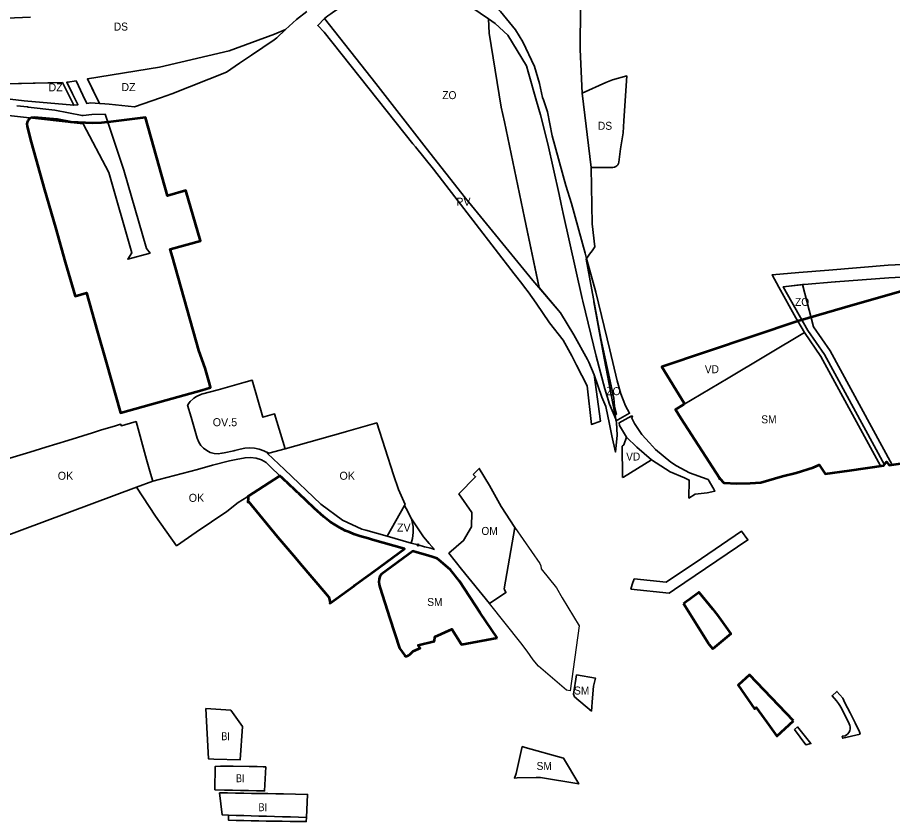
# Model space of a CAD drawing. Extents: x -650276 to -642489, y -1074311 to -1066658.
# Drawn here: x -648741 to -647428, y -1070372 to -1069166 of the extents above; entities that cross this region are included whole.
import ezdxf

# ---------------------------------------------------------------- set-up
doc = ezdxf.new("R2010")
doc.units = 0
doc.header["$LTSCALE"] = 4.8
doc.header["$PDMODE"] = 32
doc.header["$PDSIZE"] = 2.4
for name, color, linetype, lineweight in [('11', 7, 'Continuous', 35), ('12', 7, 'Continuous', 35), ('13', 7, 'Continuous', 35), ('15', 7, 'Continuous', 35), ('18', 7, 'Continuous', 35), ('2', 7, 'Continuous', 35), ('24', 7, 'Continuous', 35), ('25', 7, 'Continuous', 35), ('35', 7, 'Continuous', 35), ('40', 7, 'Continuous', 35), ('42', 7, 'Continuous', 35), ('60', 7, 'Continuous', 53), ('61', 7, 'Continuous', 25)]:
    doc.layers.add(name, color=color, linetype=linetype, lineweight=lineweight)
doc.layers.add('62', color=7, linetype='Continuous')

msp = doc.modelspace()

# ---------------------------------------------------------------- linework, layer by layer
at = {"layer": '11'}
msp.add_lwpolyline([(-648339.05, -1069812.45), (-648363.68, -1069819.31), (-648371.21, -1069815.56), (-648378.1, -1069813.29), (-648385.21, -1069811.91), (-648392.45, -1069811.44), (-648399.68, -1069811.88), (-648406.84, -1069813.23), (-648414.657, -1069815.246), (-648415.99, -1069815.59), (-648430.881, -1069818.663), (-648433.97, -1069819.3), (-648439.89, -1069819.97), (-648445.8, -1069819.51), (-648451.53, -1069817.98), (-648456.88, -1069815.39), (-648461.64, -1069811.86), (-648465.67, -1069807.49), (-648468.82, -1069802.44), (-648470.97, -1069796.9), (-648480.267, -1069765.316), (-648485.44, -1069747.39), (-648485.14, -1069746.55), (-648483.274, -1069743.777), (-648481.79, -1069741.57), (-648477.39, -1069737.44), (-648476.022, -1069736.525), (-648472.4, -1069734.1), (-648464.45, -1069730.89), (-648439.8, -1069724.19), (-648401.288, -1069713.154), (-648388.631, -1069709.738), (-648372.639, -1069765.241), (-648355.015, -1069760.287)], close=True, dxfattribs=at)
at = {"layer": '12'}
msp.add_lwpolyline([(-648057.11, -1069851.12), (-648053.61, -1069854.64), (-648078.54, -1069880.01), (-648059.32, -1069908.27), (-648059.5, -1069929.52), (-648071.58, -1069950.39), (-648093.67, -1069969.42), (-648074.96, -1069993.46), (-648032.85, -1070044.73), (-648008.18, -1070028.25), (-648010.44, -1070023.66), (-648010.94, -1070022.65), (-647994.71, -1069930.53), (-648015.11, -1069898.98), (-648032.94, -1069867.46), (-648048.08, -1069841.95)], close=True, dxfattribs=at)
at = {"layer": '13'}
msp.add_lwpolyline([(-648767.83, -1069946.87), (-648562.242, -1069870.301), (-648537.86, -1069861.22), (-648541.06, -1069849.78), (-648546.97, -1069828.68), (-648562.87, -1069771.85), (-648579.63, -1069776.66), (-648584.65, -1069778.1), (-648586.09, -1069775.75), (-648593.59, -1069778.06), (-648615.88, -1069784.93), (-648627.99, -1069788.67), (-648665.05, -1069799.99), (-648698.31, -1069810.16), (-648722.24, -1069817.54), (-648772.48, -1069832.83)], dxfattribs=at)
for points in [[(-648159.1, -1069896.39), (-648169.15, -1069873.81), (-648176.78, -1069851.74), (-648201.83, -1069773.86), (-648247.27, -1069786.64), (-648251.94, -1069787.95), (-648339.05, -1069812.45), (-648363.68, -1069819.31), (-648365.81, -1069819.9), (-648340.38, -1069843.78), (-648285.62, -1069895.71), (-648253.13, -1069919.7), (-648223.99, -1069932.96), (-648218.245, -1069934.595), (-648186.268, -1069943.697), (-648160.04, -1069897.73)], [(-648470.79, -1069843.51), (-648528.11, -1069858.73), (-648537.86, -1069861.22), (-648562.242, -1069870.301), (-648533.79, -1069913.49), (-648502.048, -1069957.969), (-648472.6, -1069937.81), (-648426.82, -1069906.88), (-648409.44, -1069893.25), (-648396.87, -1069885.43), (-648395.03, -1069884.22), (-648347.06, -1069853), (-648361.3, -1069839.7), (-648367.64, -1069833.35), (-648374.89, -1069829.22), (-648382.8, -1069826.55), (-648391.08, -1069825.45), (-648399.4, -1069825.97), (-648412.74, -1069828.72), (-648422.75, -1069830.78), (-648422.75, -1069830.78), (-648447.98, -1069837.44)]]:
    msp.add_lwpolyline(points, close=True, dxfattribs=at)
at = {"layer": '15'}
for points in [[(-648147.81, -1069355.26), (-648143.81, -1069359.39), (-648116.93, -1069393.25), (-648052.62, -1069476.32), (-647995.61, -1069549.95), (-647984.36, -1069564.49), (-647980.21, -1069569.97), (-647974.74, -1069577.39), (-647962.93, -1069594.39), (-647942.48, -1069623.82), (-647922.32, -1069649.56), (-647909.25, -1069673.35), (-647902.18, -1069687.23), (-647886.43, -1069718.16), (-647879.96, -1069776.1), (-647866.4, -1069771.43), (-647866.4, -1069771.43), (-647875.82, -1069701.85), (-647883.51, -1069682.71), (-647885.665, -1069678.788), (-647906.16, -1069641.48), (-647925.99, -1069608.57), (-647967.53, -1069559.94), (-648068.71, -1069436.57), (-648127.77, -1069361.38), (-648203.01, -1069264.73), (-648280.1, -1069166.97), (-648290.39, -1069177.69), (-648280.46, -1069187.61), (-648147.81, -1069355.26)], [(-647815.788, -1070007.72), (-647767.622, -1070012.66), (-647714.989, -1069977.087), (-647654.577, -1069936.255), (-647645.274, -1069949.279), (-647755.356, -1070023.682), (-647763.476, -1070029.17), (-647820.515, -1070023.319), (-647818.81, -1070016.41)], [(-647493.13, -1070225.217), (-647492.138, -1070227.681), (-647491.692, -1070229.974), (-647491.767, -1070233.217), (-647492.286, -1070235.393), (-647493.254, -1070237.6), (-647495.889, -1070240.926), (-647499.448, -1070243.223), (-647503.6, -1070243.95), (-647502.82, -1070246.91), (-647476.94, -1070240.79), (-647477.78, -1070237.42), (-647484.35, -1070223.91), (-647491.97, -1070208.95), (-647499.68, -1070193.54), (-647502.99, -1070186.94), (-647511.73, -1070176.61), (-647518.813, -1070183.069), (-647512.222, -1070190.785), (-647509.223, -1070194.61), (-647507.054, -1070197.854), (-647505.688, -1070200.172), (-647504.419, -1070202.575)], [(-647575.15, -1070233.71), (-647570.887, -1070229.877), (-647550.603, -1070254.911), (-647558.19, -1070256.86)], [(-647575.15, -1070233.71), (-647558.19, -1070256.86), (-647550.603, -1070254.911), (-647570.887, -1070229.877)], [(-648307.13, -1070365.57), (-648319.33, -1070365.32), (-648331.32, -1070364.96), (-648343.31, -1070364.61), (-648355.27, -1070364.25), (-648367.26, -1070363.9), (-648378.49, -1070363.57), (-648389.95, -1070363.23), (-648401.36, -1070362.89), (-648412.88, -1070362.55), (-648424.31, -1070362.21), (-648424.05, -1070370), (-648412.75, -1070370.28), (-648401.35, -1070370.5), (-648390.06, -1070370.72), (-648378.73, -1070370.94), (-648367.67, -1070371.16), (-648355.67, -1070371.28), (-648343.67, -1070371.41), (-648331.67, -1070371.53), (-648319.67, -1070371.65), (-648307.67, -1070371.78)]]:
    msp.add_lwpolyline(points, close=True, dxfattribs=at)
for points in [[(-648929.112, -1069293.123), (-648642.241, -1069324.949), (-648603.386, -1069398.357), (-648569.22, -1069518.4), (-648575.15, -1069528.35), (-648541.88, -1069518.95), (-648547.3, -1069512.136), (-648581.051, -1069394.771), (-648609.304, -1069310.668), (-648629.16, -1069310.91), (-648641.98, -1069312.45), (-648643.83, -1069312.66), (-648684.39, -1069304.67), (-648724.82, -1069299.92), (-648725.82, -1069299.81), (-648741.58, -1069298.16)], [(-647341.697, -1069532.602), (-647434.969, -1069537.141), (-647523.931, -1069544.499), (-647568.792, -1069548.21), (-647608.81, -1069551.868), (-647598.735, -1069570.026), (-647573.15, -1069616.16), (-647570.37, -1069621.18), (-647560.36, -1069638.39), (-647535.588, -1069674.163), (-647446.322, -1069838.338), (-647441.19, -1069837.6), (-647440.46, -1069836.558), (-647530.471, -1069671.013), (-647555.266, -1069635.207), (-647592.199, -1069569.411), (-647560.836, -1069566.036), (-647514.067, -1069562.282), (-647513.66, -1069562.249), (-647433.779, -1069556.106), (-647433.779, -1069556.106), (-647356.899, -1069552.034)], [(-648149.67, -1069917.83), (-648147, -1069929), (-648147, -1069938), (-648148, -1069947), (-648150, -1069954), (-648139.78, -1069956.93)], [(-648115.23, -1069963.75), (-648123.45, -1069954.79), (-648131.5, -1069944.75), (-648149.67, -1069917.83)], [(-648139.78, -1069956.93), (-648130.36, -1069959.62), (-648120.68, -1069961.63), (-648115.23, -1069963.75)]]:
    msp.add_lwpolyline(points, dxfattribs=at)
msp.add_point((-648139.78, -1069956.93), dxfattribs=at)
at = {"layer": '18'}
for points in [[(-647560.36, -1069638.39), (-647674.901, -1069706.701), (-647742.36, -1069746.93)], [(-647446.322, -1069838.338), (-647535.588, -1069674.163), (-647560.36, -1069638.39)], [(-647742.36, -1069746.93), (-647752.32, -1069752.95), (-647753.7, -1069753.9)], [(-647753.7, -1069753.9), (-647751.66, -1069757.12), (-647745.84, -1069766.71), (-647737.17, -1069780.85), (-647700.58, -1069837.2), (-647687.45, -1069857.15), (-647681.51, -1069863.72)], [(-647641.78, -1069864.26), (-647625.83, -1069863.19), (-647593.07, -1069853.74), (-647583.62, -1069851.13), (-647572.63, -1069848.63), (-647559.47, -1069844.92), (-647547.12, -1069840.87), (-647538.34, -1069836.68), (-647536.82, -1069838.87), (-647531.33, -1069847.23), (-647529.5, -1069849.99), (-647500.03, -1069846.28), (-647492.76, -1069845.02), (-647446.322, -1069838.338)], [(-647681.51, -1069863.72), (-647661.79, -1069864.92), (-647641.78, -1069864.26)], [(-648182.01, -1070067.11), (-648197.23, -1070020.37), (-648198.22, -1070016.4), (-648198.48, -1070012.3), (-648198.17, -1070008.05), (-648197.19, -1070003.94), (-648194.84, -1070000.49), (-648147.46, -1069966.19)], [(-648147.46, -1069966.19), (-648140.96, -1069968.01), (-648128.48, -1069971.7)], [(-648128.48, -1069971.7), (-648118.75, -1069974.53), (-648111.44, -1069977.32)], [(-648111.44, -1069977.32), (-648105.79, -1069981.56), (-648091.06, -1069994.07), (-648077.68, -1070011.06), (-648046.83, -1070058.62), (-648021.35, -1070096.14), (-648074.76, -1070106.17)], [(-648152.35, -1070121.05), (-648153.85, -1070122.38), (-648156.07, -1070123.54), (-648159.02, -1070123.71), (-648159.89, -1070122.49), (-648167.48, -1070111.75), (-648182.01, -1070067.11)], [(-648074.76, -1070106.17), (-648089.22, -1070083.27), (-648114.7, -1070094.68), (-648115.11, -1070101.26), (-648139.91, -1070107.48), (-648136.61, -1070111.97)], [(-648136.61, -1070111.97), (-648139.45, -1070112.79), (-648147.02, -1070116.35), (-648152.35, -1070121.05)]]:
    msp.add_lwpolyline(points, dxfattribs=at)
for points in [[(-647902.17, -1070151.64), (-647906.6, -1070180.65), (-647905.17, -1070184.5), (-647879.81, -1070206.08), (-647878.18, -1070186.33), (-647876.74, -1070168.88), (-647873.97, -1070156.58)], [(-647962.82, -1070305.9), (-647956.36, -1070305.77), (-647898.82, -1070315.51), (-647921.51, -1070276.76), (-647979.24, -1070260.71), (-647983.6, -1070259.5), (-647992.71, -1070300.01), (-647995.46, -1070306.55), (-647991.12, -1070306.46)]]:
    msp.add_lwpolyline(points, close=True, dxfattribs=at)
msp.add_point((-647687.45, -1069857.15), dxfattribs=at)
at = {"layer": '2'}
msp.add_lwpolyline([(-648458.28, -1070202.26), (-648454.038, -1070277.767), (-648446.18, -1070278.15), (-648406.8, -1070279.32), (-648403.04, -1070229.15), (-648420.7, -1070204.96)], close=True, dxfattribs=at)
for points in [[(-648368.25, -1070289.71), (-648372.1, -1070289.59), (-648380.97, -1070289.44), (-648392.94, -1070289.25), (-648416.93, -1070288.85), (-648420.39, -1070288.79), (-648428.98, -1070288.92), (-648435.93, -1070288.95), (-648444.15, -1070289.16), (-648444.85, -1070324.47)], [(-648444.85, -1070324.47), (-648444.85, -1070324.47), (-648430.02, -1070324.76), (-648418.1, -1070325), (-648406.09, -1070325.23), (-648394.08, -1070325.47), (-648382.06, -1070325.7), (-648370.07, -1070325.94), (-648368.25, -1070289.71)], [(-648307.13, -1070365.57), (-648305.47, -1070331.23), (-648341.46, -1070330.48), (-648353.32, -1070330.23), (-648365.35, -1070329.98), (-648389.43, -1070329.58), (-648401.41, -1070329.39), (-648413.45, -1070329.19), (-648425.43, -1070329), (-648437.65, -1070328.8), (-648433.46, -1070361.94), (-648424.31, -1070362.21), (-648412.88, -1070362.55)], [(-648412.88, -1070362.55), (-648401.36, -1070362.89), (-648389.95, -1070363.23), (-648378.49, -1070363.57), (-648367.26, -1070363.9), (-648355.27, -1070364.25), (-648343.31, -1070364.61), (-648331.32, -1070364.96), (-648319.33, -1070365.32)]]:
    msp.add_lwpolyline(points, dxfattribs=at)
at = {"layer": '24'}
for points in [[(-648918.889, -1069268.875), (-648673.267, -1069262.895), (-648656.242, -1069297.116), (-648650.06, -1069296.39), (-648650.58, -1069295.34), (-648658.18, -1069280.27), (-648666.827, -1069262.738), (-648665.007, -1069262.694), (-648665.007, -1069262.694), (-648652.716, -1069260.657), (-648642.74, -1069281.93), (-648636.85, -1069294.49), (-648630.82, -1069293.63), (-648617.434, -1069294.508), (-648635.818, -1069257.857), (-648527.693, -1069239.938), (-648423.173, -1069215.44), (-648354.978, -1069190.492), (-648338.523, -1069183.389), (-648322.14, -1069168.56), (-648306.83, -1069156.57)], [(-648721.315, -1069164.952), (-648781.015, -1069167.44)]]:
    msp.add_lwpolyline(points, dxfattribs=at)
msp.add_lwpolyline([(-647860.52, -1069390.72), (-647848.24, -1069390.65), (-647845.25, -1069390.07), (-647843.41, -1069389.23), (-647841.81, -1069387.99), (-647840.42, -1069386.51), (-647839.4, -1069384.73), (-647838.79, -1069382.86), (-647836.2, -1069362.68), (-647832.29, -1069338.58), (-647832.29, -1069338.58), (-647831.19, -1069320.69), (-647830.23, -1069305.38), (-647826.928, -1069253.199), (-647848.17, -1069259.21), (-647858.37, -1069263.03), (-647893.553, -1069279.017), (-647880.326, -1069390.832)], close=True, dxfattribs=at)
at = {"layer": '25'}
msp.add_line((-647862.266, -1069668.613), (-647843.449, -1069768.252), dxfattribs=at)
for points in [[(-647893.553, -1069279.017), (-647896.67, -1069213.573), (-647896.362, -1069149.171), (-647886.615, -1069053.052)], [(-648036.291, -1069139.458), (-648031.92, -1069142.67), (-648016.36, -1069156.54), (-647993.8, -1069184.11)], [(-648005.47, -1069192.09), (-648024.02, -1069174.7), (-648034.421, -1069167.61)], [(-648034.421, -1069167.61), (-648034.421, -1069167.61), (-648033, -1069189), (-648015, -1069300), (-648010.092, -1069322.087), (-647980.331, -1069465.915), (-647958.34, -1069570.699), (-647925.99, -1069608.57), (-647906.16, -1069641.48), (-647885.665, -1069678.788), (-647885.663, -1069678.794), (-647883.51, -1069682.71), (-647875.82, -1069701.85), (-647875.82, -1069701.85), (-647864.19, -1069735.12), (-647858.44, -1069749.43), (-647852.63, -1069775.7), (-647850.66, -1069785.74), (-647849.165, -1069793.367)], [(-648526.15, -1069286.21), (-648508.95, -1069280.01), (-648427.08, -1069247.75), (-648407.73, -1069233.88), (-648389.91, -1069221.86), (-648355.81, -1069198.88), (-648351.77, -1069195.88), (-648338.523, -1069183.389), (-648354.978, -1069190.492)], [(-647993.8, -1069184.11), (-647982.58, -1069202.33), (-647965.06, -1069238.95), (-647957.56, -1069264.74), (-647953.01, -1069285.73), (-647951.841, -1069289.09)], [(-648354.978, -1069190.492), (-648423.173, -1069215.44), (-648527.693, -1069239.938), (-648635.818, -1069257.857)], [(-647962.2, -1069290.88), (-647974.81, -1069246.86), (-647977.29, -1069238.21), (-648005.47, -1069192.09)], [(-648635.818, -1069257.857), (-648622.995, -1069283.455), (-648617.434, -1069294.508)], [(-648617.434, -1069294.508), (-648609.425, -1069295.033), (-648603.228, -1069295.53), (-648565.18, -1069299.46), (-648526.15, -1069286.21)], [(-647852.78, -1069745.71), (-647859.722, -1069722.428), (-647872.87, -1069673.56), (-647892.79, -1069591.06), (-647892.789, -1069591.06), (-647893.75, -1069587.08), (-647922.04, -1069459.71), (-647925.16, -1069445.68), (-647928.41, -1069431.03), (-647945.28, -1069355.1), (-647956.27, -1069311.58), (-647962.2, -1069290.88)], [(-647951.841, -1069289.09), (-647945.63, -1069306.95), (-647938.77, -1069343.17), (-647918.08, -1069417.43), (-647909.67, -1069444.46), (-647889.22, -1069519.32), (-647887.087, -1069527.229), (-647885.782, -1069525.389), (-647882.551, -1069520.835), (-647878.73, -1069515.45)], [(-647880.326, -1069390.832), (-647880.326, -1069390.832), (-647893.553, -1069279.017)], [(-647878.73, -1069515.45), (-647874.75, -1069509.84), (-647878.93, -1069475.09), (-647880.318, -1069391.297), (-647880.326, -1069390.832)], [(-647843.449, -1069768.252), (-647844.371, -1069761.991), (-647842.438, -1069760.647), (-647845.086, -1069748.753), (-647846.484, -1069736.663), (-647855.158, -1069695.232), (-647865.69, -1069647.32), (-647876.061, -1069592.206), (-647862.266, -1069668.613)], [(-647841.402, -1069792.351), (-647842.489, -1069773.282), (-647842.622, -1069770.956), (-647843.337, -1069769.013), (-647843.443, -1069768.293), (-647852.78, -1069745.71)], [(-647849.165, -1069793.367), (-647843.74, -1069817.63), (-647841.402, -1069792.351)]]:
    msp.add_lwpolyline(points, dxfattribs=at)
msp.add_lwpolyline([(-648730.66, -1069290.43), (-648656.242, -1069297.116), (-648673.267, -1069262.895), (-648761.189, -1069265.035), (-648918.889, -1069268.875), (-648909.86, -1069270.02), (-648861.49, -1069275.34), (-648785.92, -1069284.2), (-648730.66, -1069290.43)], close=True, dxfattribs=at)
msp.add_arc((-648354.978, -1069190.492), 0.000000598, 264.13978, 298.69712, dxfattribs=at)
at = {"layer": '35'}
for points in [[(-647356.899, -1069552.034), (-647433.779, -1069556.106), (-647433.779, -1069556.106), (-647513.66, -1069562.249), (-647514.067, -1069562.282), (-647560.836, -1069566.036), (-647563.104, -1069566.28)], [(-647563.104, -1069566.28), (-647546.777, -1069629.901), (-647521.943, -1069665.763)], [(-647521.943, -1069665.763), (-647428.993, -1069836.714), (-647369.3, -1069828.22)]]:
    msp.add_lwpolyline(points, dxfattribs=at)
for points in [[(-647740.74, -1069744.24), (-647742.36, -1069746.93), (-647674.901, -1069706.701), (-647560.36, -1069638.39), (-647570.37, -1069621.18), (-647701.61, -1069665.279), (-647774.11, -1069689.64)], [(-647833.172, -1069855.944), (-647833.172, -1069855.944), (-647831.62, -1069854.99), (-647789.55, -1069829.12), (-647811.83, -1069810.39), (-647827.16, -1069795.32), (-647831.32, -1069806.56), (-647833.91, -1069808.91), (-647833.2, -1069854.15)]]:
    msp.add_lwpolyline(points, close=True, dxfattribs=at)
at = {"layer": '40'}
msp.add_lwpolyline([(-648150, -1069954), (-648148, -1069947), (-648147, -1069938), (-648147, -1069929), (-648149.67, -1069917.83), (-648157.81, -1069902.06), (-648160.04, -1069897.73), (-648186.268, -1069943.697)], close=True, dxfattribs=at)
at = {"layer": '42'}
for points in [[(-648015, -1069300), (-648033, -1069189), (-648034.421, -1069167.61), (-648071.9, -1069142.06), (-648073.66, -1069140.86), (-648141.92, -1069121.66), (-648171.14, -1069122.83), (-648207.77, -1069129.95), (-648209.89, -1069130.36), (-648226.51, -1069136.57), (-648248.14, -1069144.65), (-648268.87, -1069158.61), (-648270.92, -1069159.99), (-648275.19, -1069162.87), (-648280.1, -1069166.97), (-648203.01, -1069264.73), (-648127.77, -1069361.38), (-648068.71, -1069436.57), (-647967.53, -1069559.94), (-647958.214, -1069571.3), (-647980.331, -1069465.915), (-648010.092, -1069322.087)], [(-647828.61, -1069748.41), (-647835.76, -1069730.01), (-647841.26, -1069710.69), (-647852.44, -1069664.03), (-647873.43, -1069577.87), (-647887.087, -1069527.229), (-647887.649, -1069528.021), (-647865.69, -1069647.32), (-647855.158, -1069695.232), (-647846.484, -1069736.663), (-647845.086, -1069748.753), (-647842.438, -1069760.647), (-647844.371, -1069761.991), (-647843.337, -1069769.013), (-647842.798, -1069770.477), (-647840.49, -1069769.3), (-647822.54, -1069759.29)], [(-647555.266, -1069635.207), (-647530.471, -1069671.013), (-647440.46, -1069836.558), (-647437.46, -1069832.27), (-647433.32, -1069837.33), (-647428.993, -1069836.714), (-647521.943, -1069665.763), (-647546.777, -1069629.901), (-647563.104, -1069566.28), (-647592.199, -1069569.411)], [(-647804.02, -1069791.01), (-647815.36, -1069774.66), (-647819.78, -1069765.84), (-647818.28, -1069764.99), (-647818.73, -1069763.53), (-647820.09, -1069763.65), (-647838, -1069773.63), (-647837.93, -1069777.45), (-647827.16, -1069795.32), (-647811.83, -1069810.39), (-647789.55, -1069829.12), (-647761.54, -1069847.24), (-647740.46, -1069856.29), (-647733.06, -1069859.46), (-647733.71, -1069886.65), (-647724.35, -1069880.48), (-647706.39, -1069878.81), (-647694.63, -1069876.07), (-647696.25, -1069873.35), (-647704.99, -1069858.7), (-647706.44, -1069857.98), (-647732.93, -1069848.5), (-647752.25, -1069837.95), (-647760.79, -1069832.61), (-647783.96, -1069813.49), (-647792.84, -1069803.65)]]:
    msp.add_lwpolyline(points, close=True, dxfattribs=at)
at = {"layer": '60'}
for points in [[(-648726.23, -1069329), (-648720.26, -1069352.66), (-648699.95, -1069424.34), (-648683.77, -1069480.8), (-648668.96, -1069532.87), (-648654.264, -1069583.761), (-648636.98, -1069578.86), (-648620.94, -1069635.45), (-648607.53, -1069682.78), (-648585.959, -1069758.915), (-648518.24, -1069739.91), (-648464.32, -1069724.64), (-648450.939, -1069720.921), (-648452.25, -1069716.34), (-648459.27, -1069691.81), (-648468.49, -1069665.23), (-648508.35, -1069524.48), (-648511.542, -1069513.207), (-648465.94, -1069500.68), (-648488.2, -1069425.34), (-648515.4, -1069433.05), (-648548.56, -1069315.61), (-648600.64, -1069321.87), (-648614.51, -1069323.62), (-648627.48, -1069324.05), (-648660.81, -1069322.69), (-648681.2, -1069318.86), (-648715.26, -1069315.58), (-648720.16, -1069316.01), (-648723.27, -1069318.05), (-648725.43, -1069321.26), (-648726.48, -1069324.93)], [(-648205.77, -1069996.14), (-648160.27, -1069962.63), (-648208.27, -1069949.26), (-648214.42, -1069947.46), (-648227.23, -1069943.8), (-648236.06, -1069940.52), (-648242.53, -1069937.92), (-648248.62, -1069935.54), (-648254.18, -1069932.68), (-648260.08, -1069929.44), (-648265.24, -1069926.2), (-648271.62, -1069922.1), (-648281.22, -1069914.79), (-648295.88, -1069901.64), (-648318.63, -1069879.94), (-648321, -1069877.7), (-648323.3, -1069875.52), (-648325.6, -1069873.34), (-648327.82, -1069871.23), (-648330.09, -1069869.08), (-648332.31, -1069866.98), (-648334.54, -1069864.87), (-648336.73, -1069862.79), (-648339.13, -1069860.51), (-648343.37, -1069856.49), (-648347.06, -1069853), (-648395.03, -1069884.22), (-648394.65, -1069886.59), (-648395.15, -1069892.61), (-648394.35, -1069891.95), (-648350.48, -1069944.78), (-648323.69, -1069976.45), (-648316.73, -1069984.68), (-648278.69, -1070029.47), (-648273.67, -1070035.38), (-648271.65, -1070043.3), (-648271.95, -1070044.31), (-648271.5, -1070043.98), (-648235.74, -1070018.05), (-648234.79, -1070017.36), (-648227.16, -1070011.83)], [(-647741.98, -1070044.74), (-647737.34, -1070041.32), (-647732.47, -1070037.73), (-647718.564, -1070027.479), (-647698.172, -1070052.962), (-647690.674, -1070062.331), (-647683.145, -1070072.735), (-647673.357, -1070086.635), (-647670.687, -1070090.426), (-647697.889, -1070112.941), (-647702.57, -1070106.56), (-647704.02, -1070104.5)], [(-647576.812, -1070220.636), (-647642.855, -1070151.617), (-647648.73, -1070157.05), (-647653.52, -1070161.48), (-647659.831, -1070167.317), (-647635.1, -1070202.5), (-647632.56, -1070200.72), (-647616.6, -1070223), (-647601.726, -1070243.764)]]:
    msp.add_lwpolyline(points, close=True, dxfattribs=at)
for points in [[(-647375.71, -1069564.91), (-647499.63, -1069600.73), (-647570.37, -1069621.18), (-647774.11, -1069689.64), (-647740.74, -1069744.24), (-647742.36, -1069746.93), (-647753.7, -1069753.9), (-647745.84, -1069766.71), (-647687.45, -1069857.15), (-647681.51, -1069863.72), (-647661.79, -1069864.92), (-647641.78, -1069864.26), (-647625.83, -1069863.19), (-647593.07, -1069853.74), (-647572.63, -1069848.63), (-647547.12, -1069840.87), (-647538.34, -1069836.68), (-647531.33, -1069847.23), (-647529.5, -1069849.99), (-647492.76, -1069845.02), (-647441.19, -1069837.6), (-647437.46, -1069832.27), (-647433.32, -1069837.33), (-647369.3, -1069828.22)], [(-648128.48, -1069971.7), (-648140.96, -1069968.01), (-648147.46, -1069966.19), (-648194.84, -1070000.49)], [(-648111.44, -1069977.32), (-648118.75, -1069974.53), (-648128.48, -1069971.7)], [(-648021.35, -1070096.14), (-648046.83, -1070058.62), (-648077.68, -1070011.06), (-648091.06, -1069994.07), (-648105.79, -1069981.56), (-648111.44, -1069977.32)], [(-648194.84, -1070000.49), (-648197.19, -1070003.94), (-648198.17, -1070008.05), (-648198.48, -1070012.3), (-648198.22, -1070016.4), (-648197.23, -1070020.37), (-648182.01, -1070067.11)], [(-648182.01, -1070067.11), (-648167.48, -1070111.75), (-648159.89, -1070122.49), (-648159.02, -1070123.71), (-648156.07, -1070123.54)], [(-648115.11, -1070101.26), (-648114.7, -1070094.68), (-648089.22, -1070083.27), (-648074.76, -1070106.17), (-648021.35, -1070096.14)], [(-648152.35, -1070121.05), (-648147.02, -1070116.35), (-648139.45, -1070112.79), (-648136.61, -1070111.97), (-648139.91, -1070107.48), (-648115.11, -1070101.26)], [(-648156.07, -1070123.54), (-648153.85, -1070122.38), (-648152.35, -1070121.05)]]:
    msp.add_lwpolyline(points, dxfattribs=at)
at = {"layer": '61'}
msp.add_lwpolyline([(-648008.18, -1070028.25), (-648010.94, -1070022.65), (-647994.71, -1069930.53), (-647957.24, -1069984.73), (-647955.65, -1069988.28), (-647955.08, -1069992.58), (-647932.43, -1070021.22), (-647923.61, -1070036.27), (-647898.15, -1070077.99), (-647911.88, -1070175.85), (-647917.1, -1070174.56), (-647959.1, -1070138.59), (-647967.22, -1070129.11), (-647976.36, -1070116.1), (-647985.64, -1070103.59), (-648032.85, -1070044.73)], close=True, dxfattribs=at)

# ---------------------------------------------------------------- texts
at = {"layer": '62'}
for s, width, p in [('DS', 0.95, (-648596.118, -1069185.225)), ('ZO', 0.95, (-648103.473, -1069288.058)), ('DS', 0.95, (-647870.044, -1069334.044)), ('ZO', 0.95, (-647574.423, -1069598.188)), ('VD', 0.95, (-647709.767, -1069699.204)), ('ZO', 0.95, (-647857.423, -1069732.188)), ('SM', 0.95, (-647625.077, -1069774.464)), ('VD', 0.95, (-647827.767, -1069830.204)), ('OM', 0.95, (-648044.853, -1069941.852)), ('SM', 0.95, (-648126.077, -1070048.464)), ('SM', 0.95, (-647905.887, -1070181.298)), ('BI', 0.85, (-648435.024, -1070249.825)), ('SM', 0.95, (-647962.077, -1070294.464)), ('BI', 0.85, (-648413.024, -1070312.825)), ('BI', 0.85, (-648379.14, -1070356.31))]:
    msp.add_text(s, height=12, dxfattribs=dict(at, width=width)).set_placement(p)
for s, p in [('DZ', (-648694.171, -1069276.367)), ('DZ', (-648584.843, -1069275.949)), ('PV', (-648082.5, -1069447.958)), ('OV.5', (-648447.819, -1069778.742)), ('OK', (-648680.267, -1069859.087)), ('OK', (-648257.724, -1069859.087)), ('OK', (-648483.81, -1069892.185)), ('ZV', (-648171.5, -1069936.875))]:
    msp.add_text(s, height=12, dxfattribs=at).set_placement(p)

doc.saveas('drawing.dxf')
